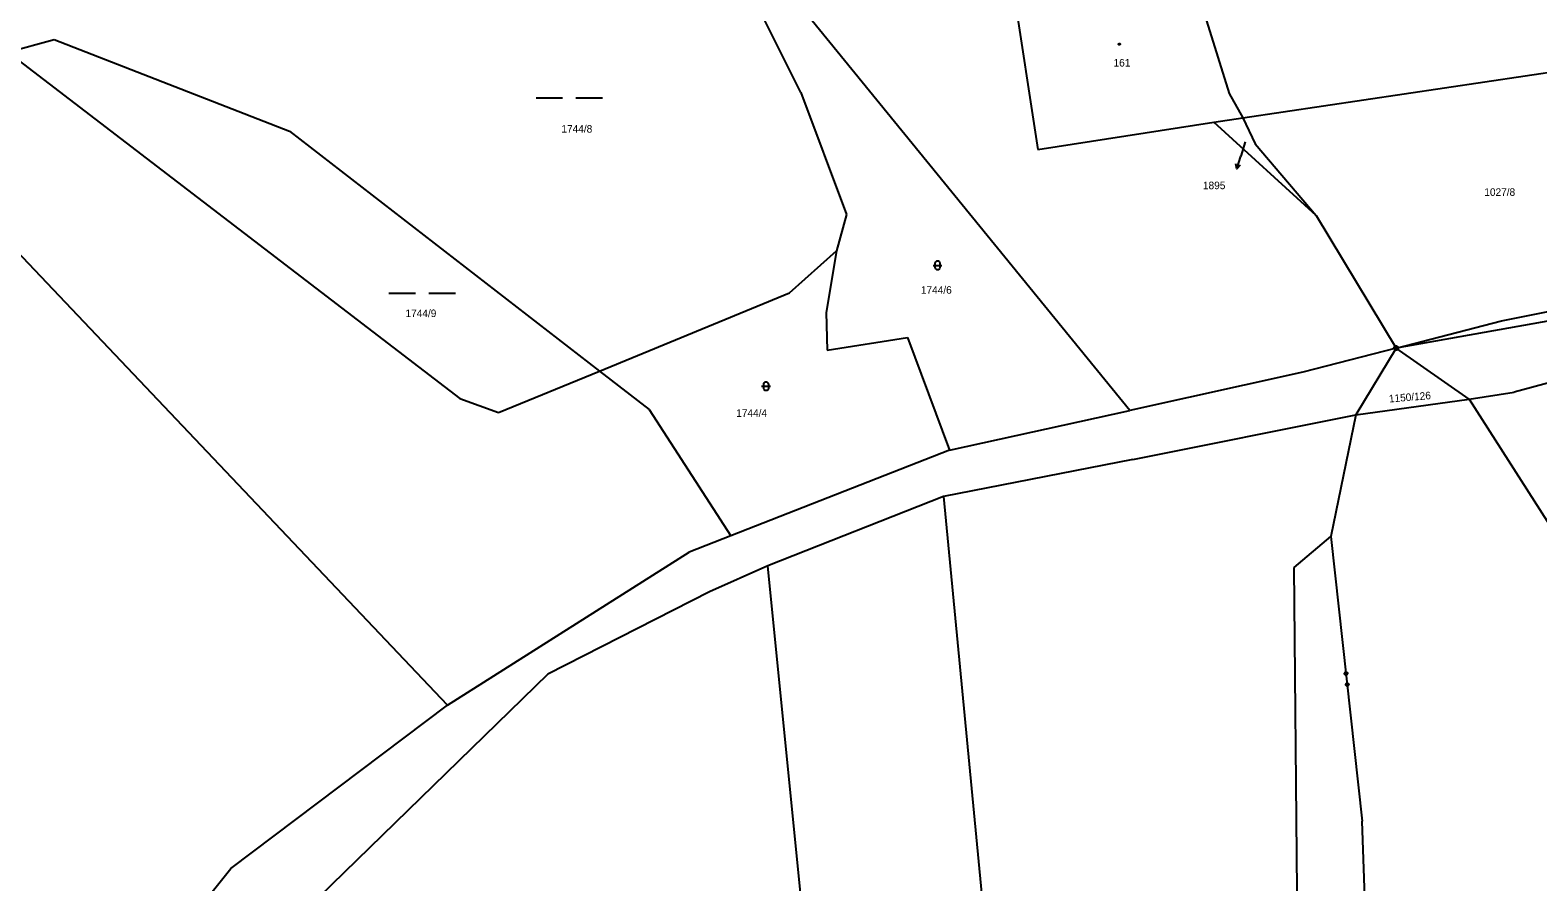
# Model space of a CAD drawing. Extents: x -747792 to -745414, y -1093712 to -1091463.
# Drawn here: x -746665.7 to -746495.9, y -1091926.9 to -1091830.9 of the extents above; entities that cross this region are included whole.
import ezdxf

# ---------------------------------------------------------------- set-up
doc = ezdxf.new("R2010")
doc.units = 0
for name, color, linetype in [('Pracovní_bod JDTM STC_VC', 7, 'Continuous'), ('Pracovní_bod JDTM STC_VC - výška', 7, 'Continuous'), ('Pracovní_bod JDTM STC_VC - číslo', 7, 'Continuous'), ('Pracovní_bod NN - výška', 7, 'Continuous'), ('Pracovní_bod polohopisu - výška', 7, 'Continuous'), ('Pracovní_bod VN - výška', 7, 'Continuous')]:
    doc.layers.add(name, color=color, linetype=linetype)

msp = doc.modelspace()

# ---------------------------------------------------------------- linework, layer by layer
at = {"layer": 'Pracovní_bod JDTM STC_VC - výška'}
msp.add_lwpolyline([(-746543.07, -1091832.39), (-746543.02, -1091832.4), (-746542.99, -1091832.44), (-746542.98, -1091832.47), (-746542.99, -1091832.52), (-746543.03, -1091832.55), (-746543.07, -1091832.55), (-746543.11, -1091832.54), (-746543.15, -1091832.51), (-746543.16, -1091832.47), (-746543.15, -1091832.42), (-746543.1, -1091832.39)], close=True, dxfattribs=at)
msp.add_lwpolyline([(-746543.07, -1091832.39), (-746543.02, -1091832.4), (-746542.99, -1091832.44), (-746542.98, -1091832.47), (-746542.99, -1091832.52), (-746543.03, -1091832.55), (-746543.07, -1091832.55), (-746543.11, -1091832.54), (-746543.15, -1091832.51), (-746543.16, -1091832.47), (-746543.15, -1091832.42), (-746543.1, -1091832.39)], close=True, dxfattribs=at)
at = {"layer": 'Pracovní_bod JDTM STC_VC - číslo'}
for points in [[(-746608.77, -1091838.51), (-746605.77, -1091838.51)], [(-746604.27, -1091838.51), (-746601.27, -1091838.51)], [(-746564.05, -1091857.39), (-746563.42, -1091857.39), (-746563.05, -1091857.39)], [(-746625.35, -1091860.52), (-746622.35, -1091860.52)], [(-746620.85, -1091860.52), (-746617.85, -1091860.52)], [(-746583.36, -1091871.01), (-746582.72, -1091871.01), (-746582.36, -1091871.01)]]:
    msp.add_lwpolyline(points, dxfattribs=at)
for points in [[(-746563.8, -1091857.14), (-746563.75, -1091856.99), (-746563.62, -1091856.9), (-746563.47, -1091856.9), (-746563.34, -1091856.99), (-746563.3, -1091857.14), (-746563.3, -1091857.64), (-746563.34, -1091857.78), (-746563.47, -1091857.88), (-746563.62, -1091857.88), (-746563.75, -1091857.78), (-746563.8, -1091857.64)], [(-746583.11, -1091870.76), (-746583.06, -1091870.61), (-746582.94, -1091870.52), (-746582.78, -1091870.52), (-746582.66, -1091870.61), (-746582.6, -1091870.76), (-746582.6, -1091871.26), (-746582.66, -1091871.41), (-746582.78, -1091871.5), (-746582.94, -1091871.5), (-746583.06, -1091871.41), (-746583.11, -1091871.26)]]:
    msp.add_lwpolyline(points, close=True, dxfattribs=at)
at = {"layer": 'Pracovní_bod NN - výška'}
for points in [[(-746541.9, -1091873.74), (-746598.54, -1091804.19)], [(-746578.94, -1091837.92), (-746587.63, -1091820.54)], [(-746555.07, -1091825.96), (-746552.26, -1091844.32)], [(-746533.26, -1091829.85), (-746530.7, -1091838.03)], [(-746533.26, -1091829.85), (-746530.7, -1091838.03)], [(-746668.26, -1091833.36), (-746663.04, -1091831.93)], [(-746663.04, -1091831.93), (-746636.54, -1091842.26)], [(-746668.26, -1091833.36), (-746617.36, -1091872.4)], [(-746529.15, -1091840.76), (-746488.29, -1091834.69)], [(-746578.94, -1091837.92), (-746573.8, -1091851.67)], [(-746530.7, -1091838.03), (-746529.15, -1091840.76)], [(-746530.7, -1091838.03), (-746529.15, -1091840.76)], [(-746636.54, -1091842.26), (-746601.63, -1091869.3)], [(-746552.26, -1091844.32), (-746532.44, -1091841.27)], [(-746532.44, -1091841.27), (-746529.15, -1091840.76)], [(-746520.89, -1091851.77), (-746532.44, -1091841.27)], [(-746529.15, -1091840.76), (-746527.77, -1091843.71)], [(-746529.15, -1091840.76), (-746527.77, -1091843.71)], [(-746527.77, -1091843.71), (-746520.89, -1091851.77)], [(-746527.77, -1091843.71), (-746520.89, -1091851.77)], [(-746618.72, -1091906.94), (-746672.88, -1091849.9)], [(-746573.8, -1091851.67), (-746574.94, -1091855.75)], [(-746520.89, -1091851.77), (-746511.89, -1091866.71)], [(-746520.89, -1091851.77), (-746511.89, -1091866.71)], [(-746580.21, -1091860.48), (-746574.94, -1091855.75)], [(-746574.94, -1091855.75), (-746576.07, -1091862.71)], [(-746466.76, -1091858.69), (-746511.89, -1091866.71)], [(-746500.03, -1091863.63), (-746475.22, -1091858.67)], [(-746601.63, -1091869.3), (-746580.21, -1091860.48)], [(-746576.07, -1091862.71), (-746575.96, -1091866.94)], [(-746511.89, -1091866.71), (-746500.03, -1091863.63)], [(-746469.91, -1091863.95), (-746498.59, -1091871.67)], [(-746575.96, -1091866.94), (-746566.91, -1091865.53)], [(-746566.91, -1091865.53), (-746562.21, -1091878.22)], [(-746511.89, -1091866.71), (-746522.41, -1091869.43)], [(-746511.89, -1091866.71), (-746516.44, -1091874.23)], [(-746511.89, -1091866.71), (-746516.44, -1091874.23)], [(-746503.67, -1091872.47), (-746511.89, -1091866.71)], [(-746613.01, -1091873.98), (-746601.63, -1091869.3)], [(-746601.63, -1091869.3), (-746596.04, -1091873.63)], [(-746522.41, -1091869.43), (-746541.9, -1091873.74)], [(-746617.36, -1091872.4), (-746613.01, -1091873.98)], [(-746516.44, -1091874.23), (-746503.67, -1091872.47)], [(-746503.67, -1091872.47), (-746498.59, -1091871.67)], [(-746503.67, -1091872.47), (-746465, -1091932.97)], [(-746596.04, -1091873.63), (-746586.81, -1091887.86)], [(-746562.21, -1091878.22), (-746541.9, -1091873.74)], [(-746541.55, -1091879.27), (-746516.44, -1091874.23)], [(-746516.44, -1091874.23), (-746519.23, -1091887.95)], [(-746516.44, -1091874.23), (-746519.23, -1091887.95)], [(-746562.21, -1091878.22), (-746586.81, -1091887.86)], [(-746541.55, -1091879.27), (-746562.86, -1091883.43)], [(-746562.86, -1091883.43), (-746582.66, -1091891.25)], [(-746562.86, -1091883.43), (-746557.88, -1091935.53)], [(-746586.81, -1091887.86), (-746591.51, -1091889.7)], [(-746523.39, -1091891.42), (-746519.23, -1091887.95)], [(-746519.23, -1091887.95), (-746515.71, -1091920)], [(-746519.23, -1091887.95), (-746515.71, -1091920)], [(-746618.72, -1091906.94), (-746591.51, -1091889.7)], [(-746582.66, -1091891.25), (-746589.23, -1091894.16)], [(-746575.64, -1091961.5), (-746582.66, -1091891.25)], [(-746523.03, -1091927.86), (-746523.39, -1091891.42)], [(-746589.23, -1091894.16), (-746607.44, -1091903.47)], [(-746607.44, -1091903.47), (-746634.7, -1091929.99)], [(-746517.37, -1091903.43), (-746517.45, -1091903.53), (-746517.59, -1091903.55), (-746517.69, -1091903.46), (-746517.71, -1091903.33), (-746517.62, -1091903.22), (-746517.49, -1091903.21), (-746517.38, -1091903.29), (-746517.37, -1091903.43), (-746517.39, -1091903.42), (-746517.4, -1091903.3), (-746517.45, -1091903.27), (-746517.43, -1091903.47), (-746517.46, -1091903.51), (-746517.49, -1091903.23), (-746517.53, -1091903.24), (-746517.5, -1091903.52), (-746517.54, -1091903.52), (-746517.57, -1091903.24), (-746517.61, -1091903.25), (-746517.58, -1091903.52), (-746517.62, -1091903.49), (-746517.65, -1091903.29), (-746517.68, -1091903.33), (-746517.67, -1091903.45)], [(-746517.37, -1091903.43), (-746517.45, -1091903.53), (-746517.59, -1091903.55), (-746517.69, -1091903.46), (-746517.71, -1091903.33), (-746517.62, -1091903.22), (-746517.49, -1091903.21), (-746517.38, -1091903.29), (-746517.37, -1091903.43), (-746517.39, -1091903.42), (-746517.4, -1091903.3), (-746517.45, -1091903.27), (-746517.43, -1091903.47), (-746517.46, -1091903.51), (-746517.49, -1091903.23), (-746517.53, -1091903.24), (-746517.5, -1091903.52), (-746517.54, -1091903.52), (-746517.57, -1091903.24), (-746517.61, -1091903.25), (-746517.58, -1091903.52), (-746517.62, -1091903.49), (-746517.65, -1091903.29), (-746517.68, -1091903.33), (-746517.67, -1091903.45)], [(-746517.23, -1091904.67), (-746517.32, -1091904.77), (-746517.45, -1091904.79), (-746517.56, -1091904.7), (-746517.57, -1091904.57), (-746517.49, -1091904.46), (-746517.35, -1091904.45), (-746517.25, -1091904.53), (-746517.23, -1091904.67), (-746517.25, -1091904.66), (-746517.27, -1091904.54), (-746517.31, -1091904.5), (-746517.29, -1091904.7), (-746517.33, -1091904.74), (-746517.36, -1091904.47), (-746517.4, -1091904.47), (-746517.36, -1091904.75), (-746517.4, -1091904.75), (-746517.44, -1091904.47), (-746517.48, -1091904.48), (-746517.44, -1091904.76), (-746517.49, -1091904.72), (-746517.51, -1091904.52), (-746517.55, -1091904.57), (-746517.53, -1091904.69)], [(-746517.23, -1091904.67), (-746517.32, -1091904.77), (-746517.45, -1091904.79), (-746517.56, -1091904.7), (-746517.57, -1091904.57), (-746517.49, -1091904.46), (-746517.35, -1091904.45), (-746517.25, -1091904.53), (-746517.23, -1091904.67), (-746517.25, -1091904.66), (-746517.27, -1091904.54), (-746517.31, -1091904.5), (-746517.29, -1091904.7), (-746517.33, -1091904.74), (-746517.36, -1091904.47), (-746517.4, -1091904.47), (-746517.36, -1091904.75), (-746517.4, -1091904.75), (-746517.44, -1091904.47), (-746517.48, -1091904.48), (-746517.44, -1091904.76), (-746517.49, -1091904.72), (-746517.51, -1091904.52), (-746517.55, -1091904.57), (-746517.53, -1091904.69)], [(-746643.14, -1091925.36), (-746618.72, -1091906.94)], [(-746514.04, -1091968.16), (-746515.71, -1091920)], [(-746514.04, -1091968.16), (-746515.71, -1091920)], [(-746664.61, -1091952.21), (-746643.14, -1091925.36)]]:
    msp.add_lwpolyline(points, dxfattribs=at)
at = {"layer": 'Pracovní_bod polohopisu - výška'}
for points in [[(-746528.9, -1091843.48), (-746529.4, -1091845.09)], [(-746529.84, -1091846.52), (-746529.4, -1091845.09)], [(-746529.46, -1091846.12), (-746529.84, -1091846.52), (-746529.93, -1091845.97)]]:
    msp.add_lwpolyline(points, dxfattribs=at)
at = {"layer": 'Pracovní_bod VN - výška'}
msp.add_lwpolyline([(-746511.82, -1091866.47), (-746511.69, -1091866.56), (-746511.64, -1091866.71), (-746511.69, -1091866.85), (-746511.82, -1091866.95), (-746511.97, -1091866.95), (-746512.09, -1091866.85), (-746512.14, -1091866.71), (-746512.09, -1091866.56), (-746511.97, -1091866.47)], close=True, dxfattribs=at)
msp.add_lwpolyline([(-746511.92, -1091866.71), (-746511.86, -1091866.71)], dxfattribs=at)

# ---------------------------------------------------------------- texts
at = {"layer": 'Pracovní_bod JDTM STC_VC'}
for s, height, p in [('161', 0.85, (-746543.72, -1091834.99)), ('1744/8', 0.85, (-746605.91, -1091842.44)), ('1895', 0.05, (-746528.97, -1091843.48)), ('1027/8', 0.85, (-746501.96, -1091849.56)), ('1744/6', 0.85, (-746565.42, -1091860.59)), ('1744/9', 0.85, (-746623.47, -1091863.22)), ('1744/4', 0.85, (-746586.22, -1091874.46))]:
    msp.add_text(s, height=height, dxfattribs=at).set_placement(p)
msp.add_text('1150/126', height=0.85, rotation=4.7555, dxfattribs=at).set_placement((-746512.67, -1091872.85))
at = {"layer": 'Pracovní_bod polohopisu - výška'}
msp.add_text('1895', height=0.85, dxfattribs=at).set_placement((-746533.65, -1091848.81))

doc.saveas('drawing.dxf')
